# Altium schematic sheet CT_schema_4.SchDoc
size 369 x 245 mm
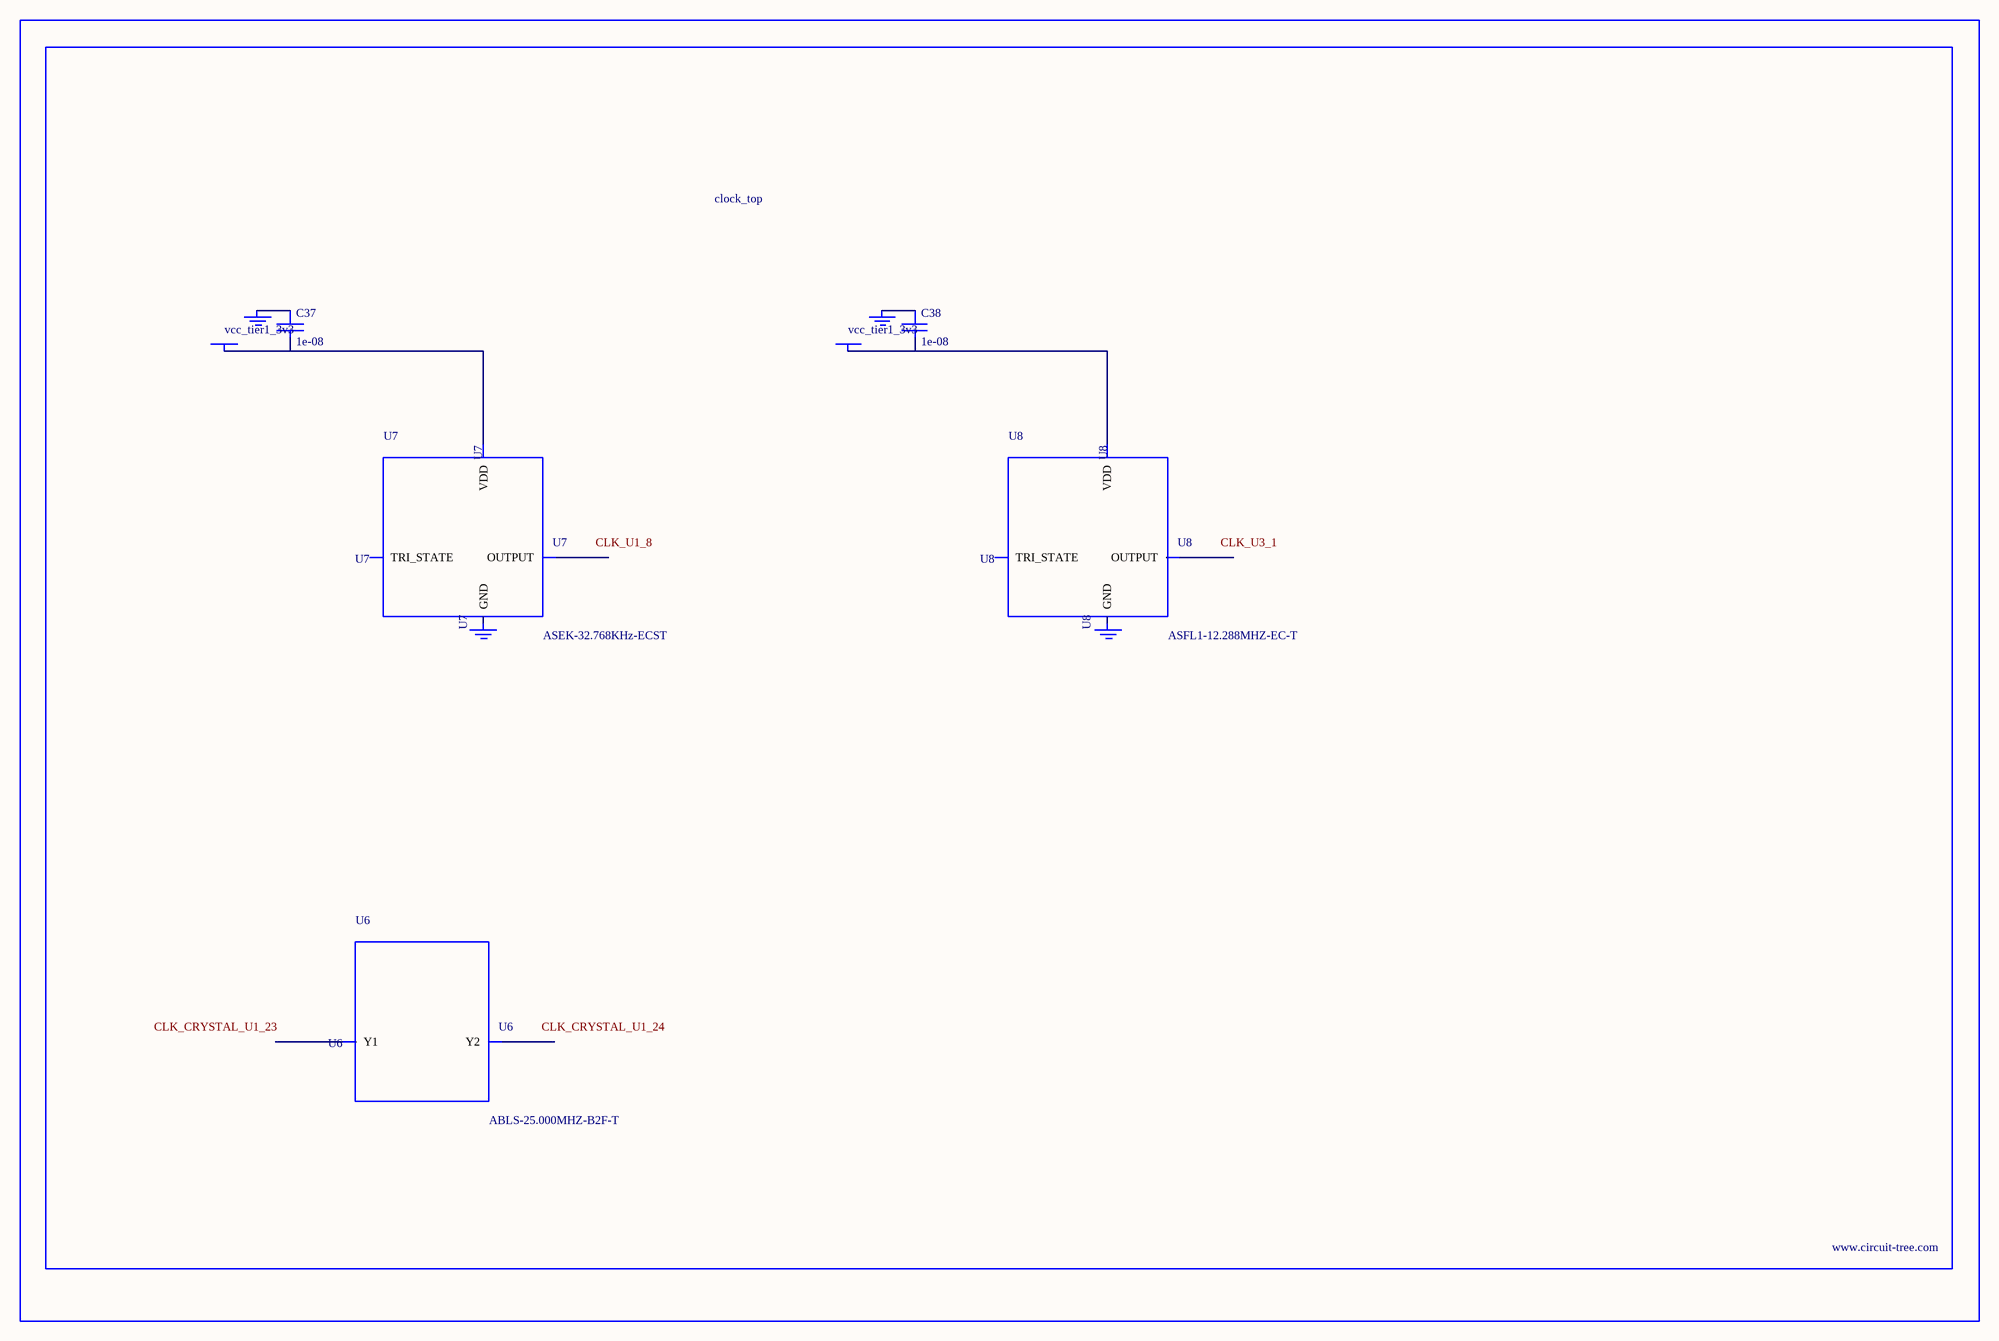
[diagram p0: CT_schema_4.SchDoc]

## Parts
BORDER3  (no value)
C37  1e-08  [C0402]
C38  1e-08  [C0402]
GND_INSTANCE_3_0  (no value)
GND_INSTANCE_3_1  (no value)
GND_INSTANCE_3_2  (no value)
GND_INSTANCE_3_3  (no value)
POWER_INSTANCE_3_0  vcc_tier1_3v3
POWER_INSTANCE_3_1  vcc_tier1_3v3
U6  ABLS-25.000MHZ-B2F-T  [ABLS-25.000MHZ-B2F-T]
U7  ASEK-32.768KHz-ECST  [ASEK]
U8  ASFL1-12.288MHZ-EC-T  [ASFL1]

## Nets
NetC37_1: C37.1 GND_INSTANCE_3_0.0(GND)
NetC37_2: C37.2 POWER_INSTANCE_3_0.0(PWR) U7.4(VDD)
NetC38_1: C38.1 GND_INSTANCE_3_2.0(GND)
NetC38_2: C38.2 POWER_INSTANCE_3_1.0(PWR) U8.4(VDD)

Not connected (* = marked no-connect by the designer): GND_INSTANCE_3_1 0(GND); GND_INSTANCE_3_3 0(GND); U6 1(Y1) 2(Y2); U7 1(TRI_STATE) 2(GND) 3(OUTPUT); U8 1(TRI_STATE) 2(GND) 3(OUTPUT)

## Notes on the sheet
- Labels drawn without touching a wire or pin: CLK_CRYSTAL_U1_23, CLK_CRYSTAL_U1_24, CLK_U1_8, CLK_U3_1

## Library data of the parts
BORDER3 = BORDER_PAGE3
C37 C38 = C0402C103K3RAC
GND_INSTANCE_3_0-GND_INSTANCE_3_3 = GND
POWER_INSTANCE_3_0 POWER_INSTANCE_3_1 = PWR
